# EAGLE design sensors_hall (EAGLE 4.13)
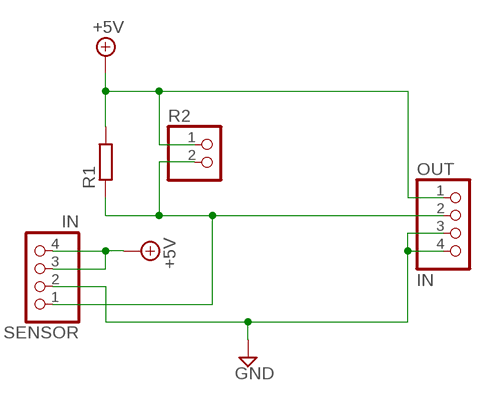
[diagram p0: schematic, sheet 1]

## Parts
OUT  IN  PINHD-1X4  [1X04]
R1  R-EU_0204/7  [0204/7]
R2  PINHD-1X2  [1X02]
SENSOR  IN  PINHD-1X4  [1X04]

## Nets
+5V: OUT.1 R1.2 R2.1 SENSOR.3 SENSOR.4
GND: OUT.3 OUT.4 SENSOR.2
N$1: OUT.2 R1.1 R2.2 SENSOR.1

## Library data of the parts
OUT SENSOR = pinhead:PINHD-1X4: PIN HEADER
R1 = rcl:R-EU_: RESISTOR, European symbol
R2 = pinhead:PINHD-1X2: PIN HEADER

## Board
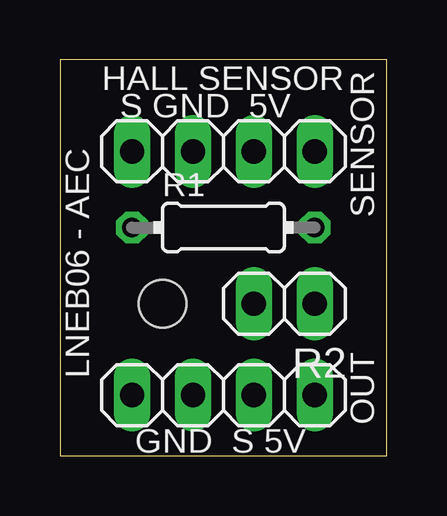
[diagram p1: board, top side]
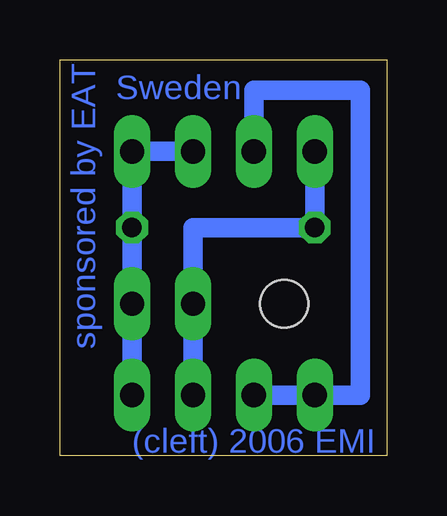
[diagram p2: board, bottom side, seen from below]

Size 13.64 x 16.5 mm. Coordinates in mm from the lower left corner, seen from the top.
Outline: 0,0 13.64,0 13.64,16.5 0,16.5 0,0
Copper layers (1*16): Top 0.035mm / dielectric 1.5mm / Bottom 0.035mm
Design rules "default": minimum track width 10mil, minimum drill 24mil, track to track 8mil, track to pad 8mil, pad to pad 8mil, via to via 8mil, smd to smd 8mil, copper to edge 40mil, drill to drill 8mil, minimum pad ring 10mil, minimum via ring 8mil, stop-mask expansion 4mil, vias tented up to drill 0mil, thermal gap 10mil
Holes 2 mm at 4.28,6.34

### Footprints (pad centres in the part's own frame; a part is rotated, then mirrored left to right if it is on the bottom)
1X04 = drill 1.016 long: 1 -3.81,0; 2 -1.27,0; 3 1.27,0; 4 3.81,0
0204/7 = drill 0.813 octagon: 1 -3.81,0; 2 3.81,0
1X02 = drill 1.016 long: 1 -1.27,0; 2 1.27,0

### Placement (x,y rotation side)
OUT  6.82,2.54 180 top
R1  6.82,9.52 0 top
R2  9.36,6.34 180 top
SENSOR  6.82,12.7 0 top

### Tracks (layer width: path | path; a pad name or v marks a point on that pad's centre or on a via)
+5V
  Bottom 0.61: R2.1 OUT.1
  Bottom 0.813: OUT.1 R2.1 R1.2 SENSOR.4 SENSOR.3
GND
  Bottom 0.61: OUT.3 OUT.4
  Bottom 0.813: SENSOR.2 5.55,15.24 1.1,15.24 1.1,2.54 OUT.4 OUT.3
N$1
  Bottom 0.61: OUT.2 R2.2
  Bottom 0.813: SENSOR.1 R1.1 8.09,9.52 R2.2 OUT.2

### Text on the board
Bottom: sponsored by EAT | Sweden | (cleft) 2006 EMI
tPlace: HALL SENSOR | S GND 5V | LNEB06 - AEC | GND S 5V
